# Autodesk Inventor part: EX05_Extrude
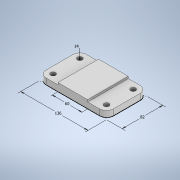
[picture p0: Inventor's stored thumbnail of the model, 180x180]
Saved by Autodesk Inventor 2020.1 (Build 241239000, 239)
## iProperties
Created: 2019-10
Part Number: EX05_Extrude
Material: Generic
Document SubType Name: Modeling
Designer: Synergysoft Dell02
Density: 1 g/cm^3
Appearance: Default
Author: Synergysoft Dell02
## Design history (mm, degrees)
sketch "Sketch1"
  geometry: L1 (54, -41)-(-54, -41); L2 (-68, -27)-(-68, 27); L3 (-54, 41)-(54, 41); L4 (68, 27)-(68, -27); L5 (68, -41)-(-68, 41); L6 (-68, -41)-(68, 41); L7 (30, -41)-(-30, -41); L8 (-30, -41)-(-30, 41); L9 (-30, 41)-(30, 41); L10 (30, 41)-(30, -41); L11 (30, -41)-(-30, 41); L12 (-30, -41)-(30, 41); A1 r 14 centre (54, -27) between (54, -41) and (68, -27); A2 r 14 centre (-54, -27) between (-68, -27) and (-54, -41); A3 r 14 centre (-54, 27) between (-54, 41) and (-68, 27); A4 r 14 centre (54, 27) between (68, 27) and (54, 41); 4 further points
  constraints: 24 end point, 9 point on line, 8 point on circle, 8 tangent, 4 centre point, 4 midpoint, 4 parallel, 3 equal radius, 2 horizontal, 2 perpendicular
  dimensions: "d0" = 136 distance of L5.end L6.end; "d1" = 82 distance of L6.start L5.end; "d2" = 60 distance of L8.end L9.end; "d3" = 14 radius of A1
extrude "Extrusion1" new body sketch "Sketch1" distance "d4" = 12; taper "d5" = 0 deg
extrude "Extrusion2" join sketch "Sketch1" distance "d6" = 16; taper "d7" = 0 deg
sketch "Sketch2"
  geometry: L1 (-68, 27)-(-68, -27) reference; L2 (-30, 41)-(-54, 41) reference; C1 r 5 at (-54, 27); C2 r 5 at (54, 27); C3 r 5 at (-54, -27); C4 r 5 at (54, -27); 1 further point
  constraints: 4 centre point, 1 horizontal, 1 vertical, 6 other
  dimensions: "d8" = 10 diameter of C1; "d9" = 14 distance from line of C1.centre L1; "d10" = 14 distance from line of L2 C1.centre; "d13" = 108 distance of C1.centre C2.centre; "d16" = 54 distance of C1.centre C3.centre
extrude "Extrusion4" cut sketch "Sketch2" distance "d21" = 12; taper "d22" = 0 deg
body "Solid1"
